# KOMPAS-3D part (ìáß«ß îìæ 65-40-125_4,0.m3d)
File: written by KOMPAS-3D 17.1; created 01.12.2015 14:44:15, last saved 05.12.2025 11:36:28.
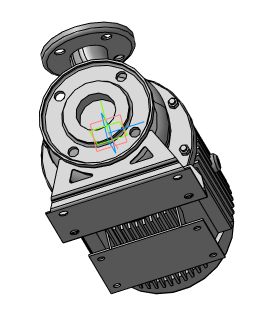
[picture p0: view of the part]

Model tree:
1. Операция без истории:3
